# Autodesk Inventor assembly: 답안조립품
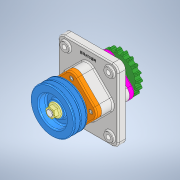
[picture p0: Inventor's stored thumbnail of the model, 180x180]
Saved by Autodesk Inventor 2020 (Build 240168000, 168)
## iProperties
Created: 2021-07
Part Number: 답안조립품
Document SubType Name: Assembly
Designer: Owner
Author: Owner
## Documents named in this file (16)
- C:\Users\Owner\Desktop\710707V1014\710707V1014\답안조립품.iam
- C:\Users\Owner\Desktop\710707V1014\710707V1014\본체.ipt
- C:\Users\Owner\Desktop\710707V1014\710707V1014\M16 너트.ipt
- C:\Users\Owner\Desktop\710707V1014\710707V1014\V-벨트풀리.ipt
- C:\Users\Owner\Desktop\710707V1014\710707V1014\멈춤나사 M4.ipt
- C:\Users\Owner\Desktop\710707V1014\710707V1014\베어링 6206.ipt
- C:\Users\Owner\Desktop\710707V1014\710707V1014\볼트 M6.ipt
- C:\Users\Owner\Desktop\710707V1014\710707V1014\부시.ipt
- C:\Users\Owner\Desktop\710707V1014\710707V1014\오일실 30x42x8.ipt
- C:\Users\Owner\Desktop\710707V1014\710707V1014\오일실 30x45x8.ipt
- C:\Users\Owner\Desktop\710707V1014\710707V1014\체인 스프로킷.ipt
- C:\Users\Owner\Desktop\710707V1014\710707V1014\축.ipt
- C:\Users\Owner\Desktop\710707V1014\710707V1014\커버A.ipt
- C:\Users\Owner\Desktop\710707V1014\710707V1014\커버B.ipt
- C:\Users\Owner\Desktop\710707V1014\710707V1014\키 6x6x18.ipt
- C:\Users\Owner\Desktop\710707V1014\710707V1014\키 6x6x20.ipt
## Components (3 placed, 2 different names)
1. M16 너트:1 — 각도:3
2. V-벨트풀리:1 — 각도:1
3. M16 너트:2 — 각도:4
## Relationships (3: Angle 3)
- 각도:1 [Angle]: V-벨트풀리:1
- 각도:3 [Angle]: M16 너트:1
- 각도:4 [Angle]: M16 너트:2
